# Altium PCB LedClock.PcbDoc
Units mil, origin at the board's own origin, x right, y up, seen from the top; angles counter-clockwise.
Board outline 2110 x 1975 mil, 2 copper layers (Top Layer, Bottom Layer); 29 components, 43 nets, 157 pads, 18 vias.
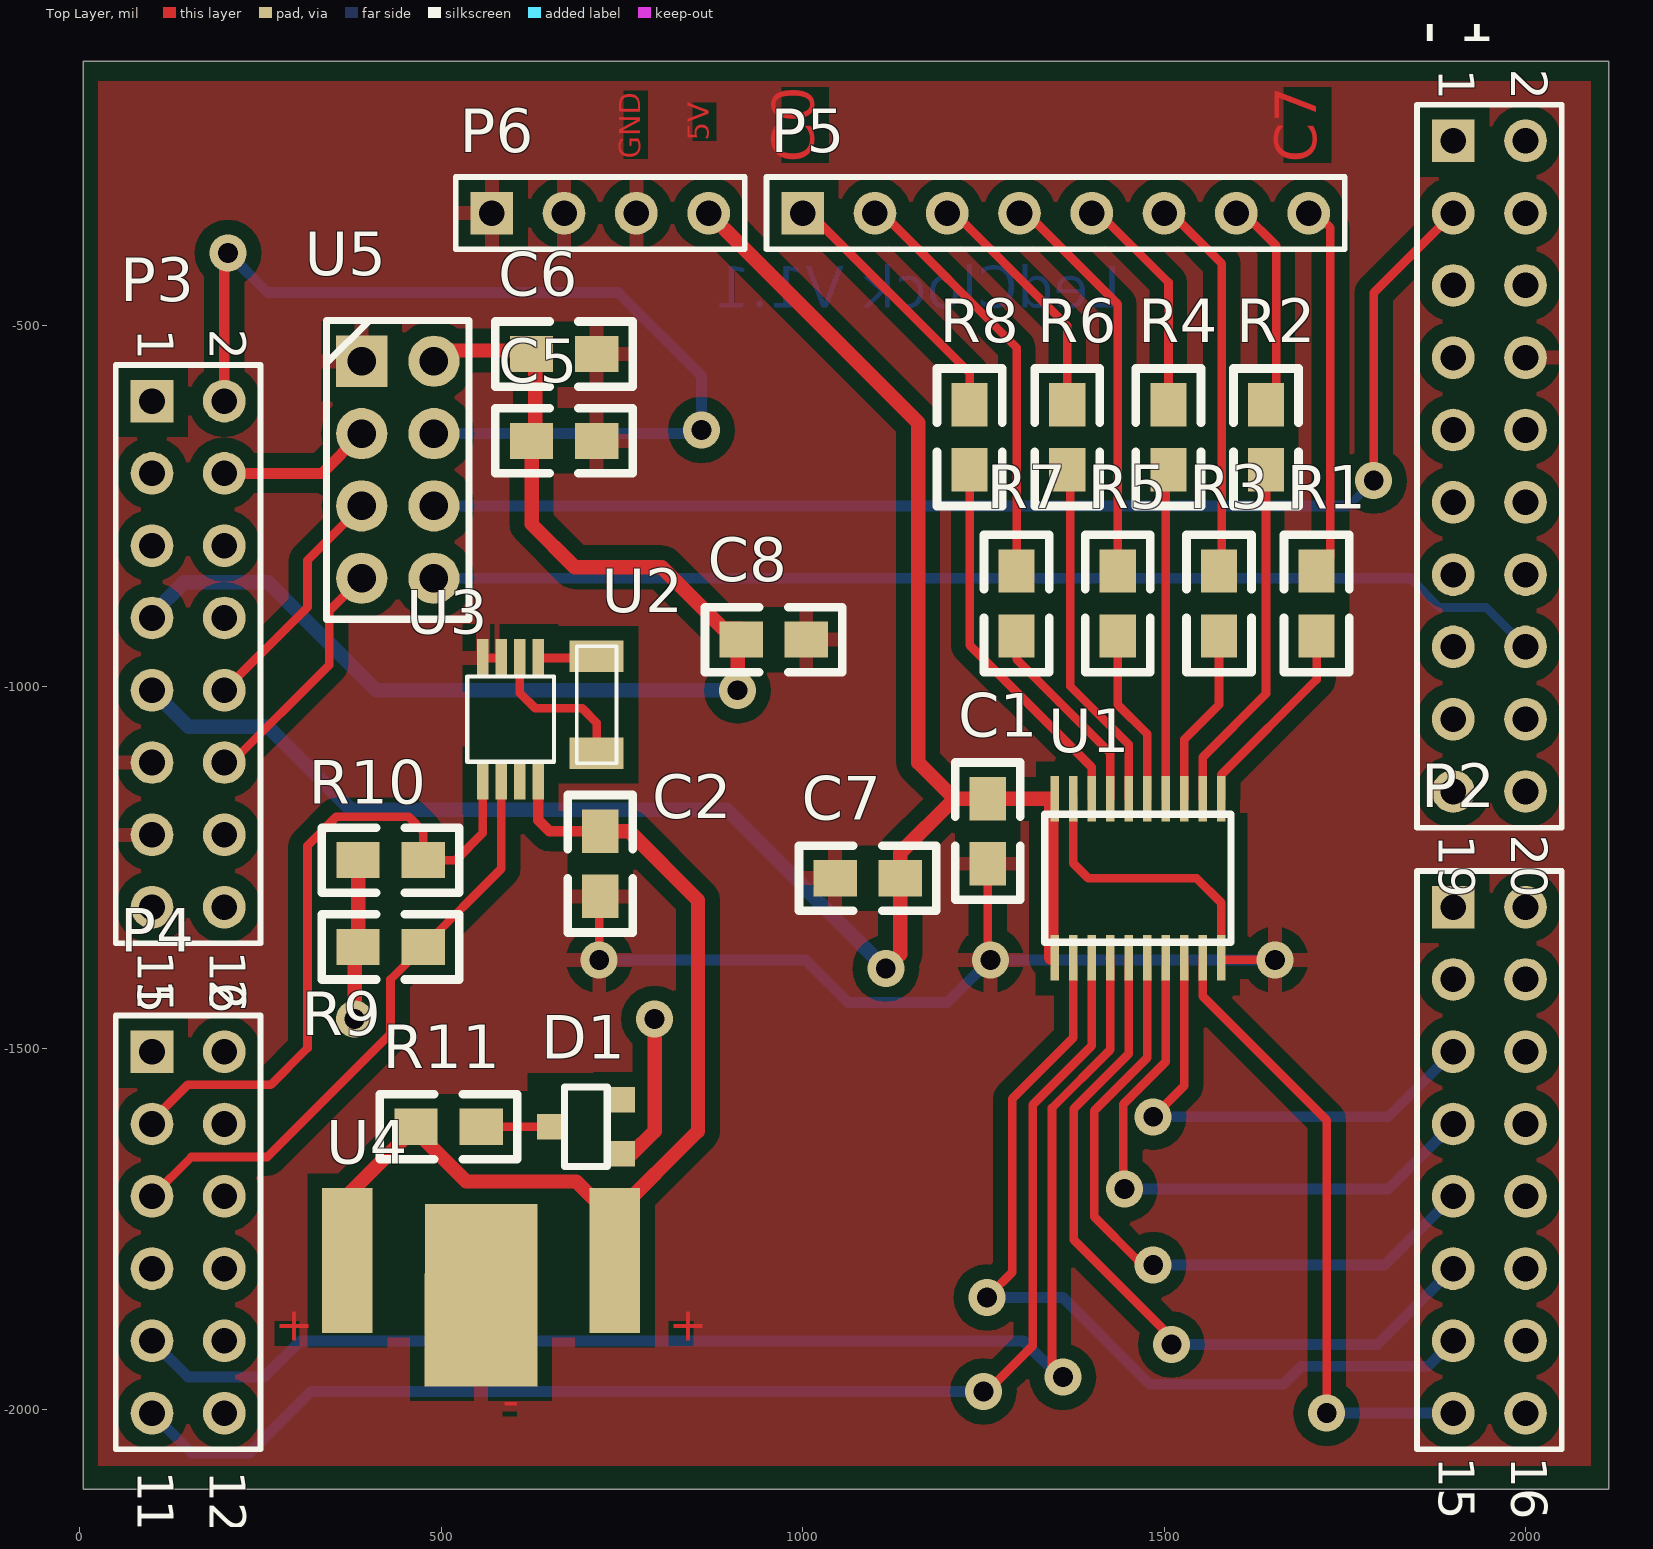
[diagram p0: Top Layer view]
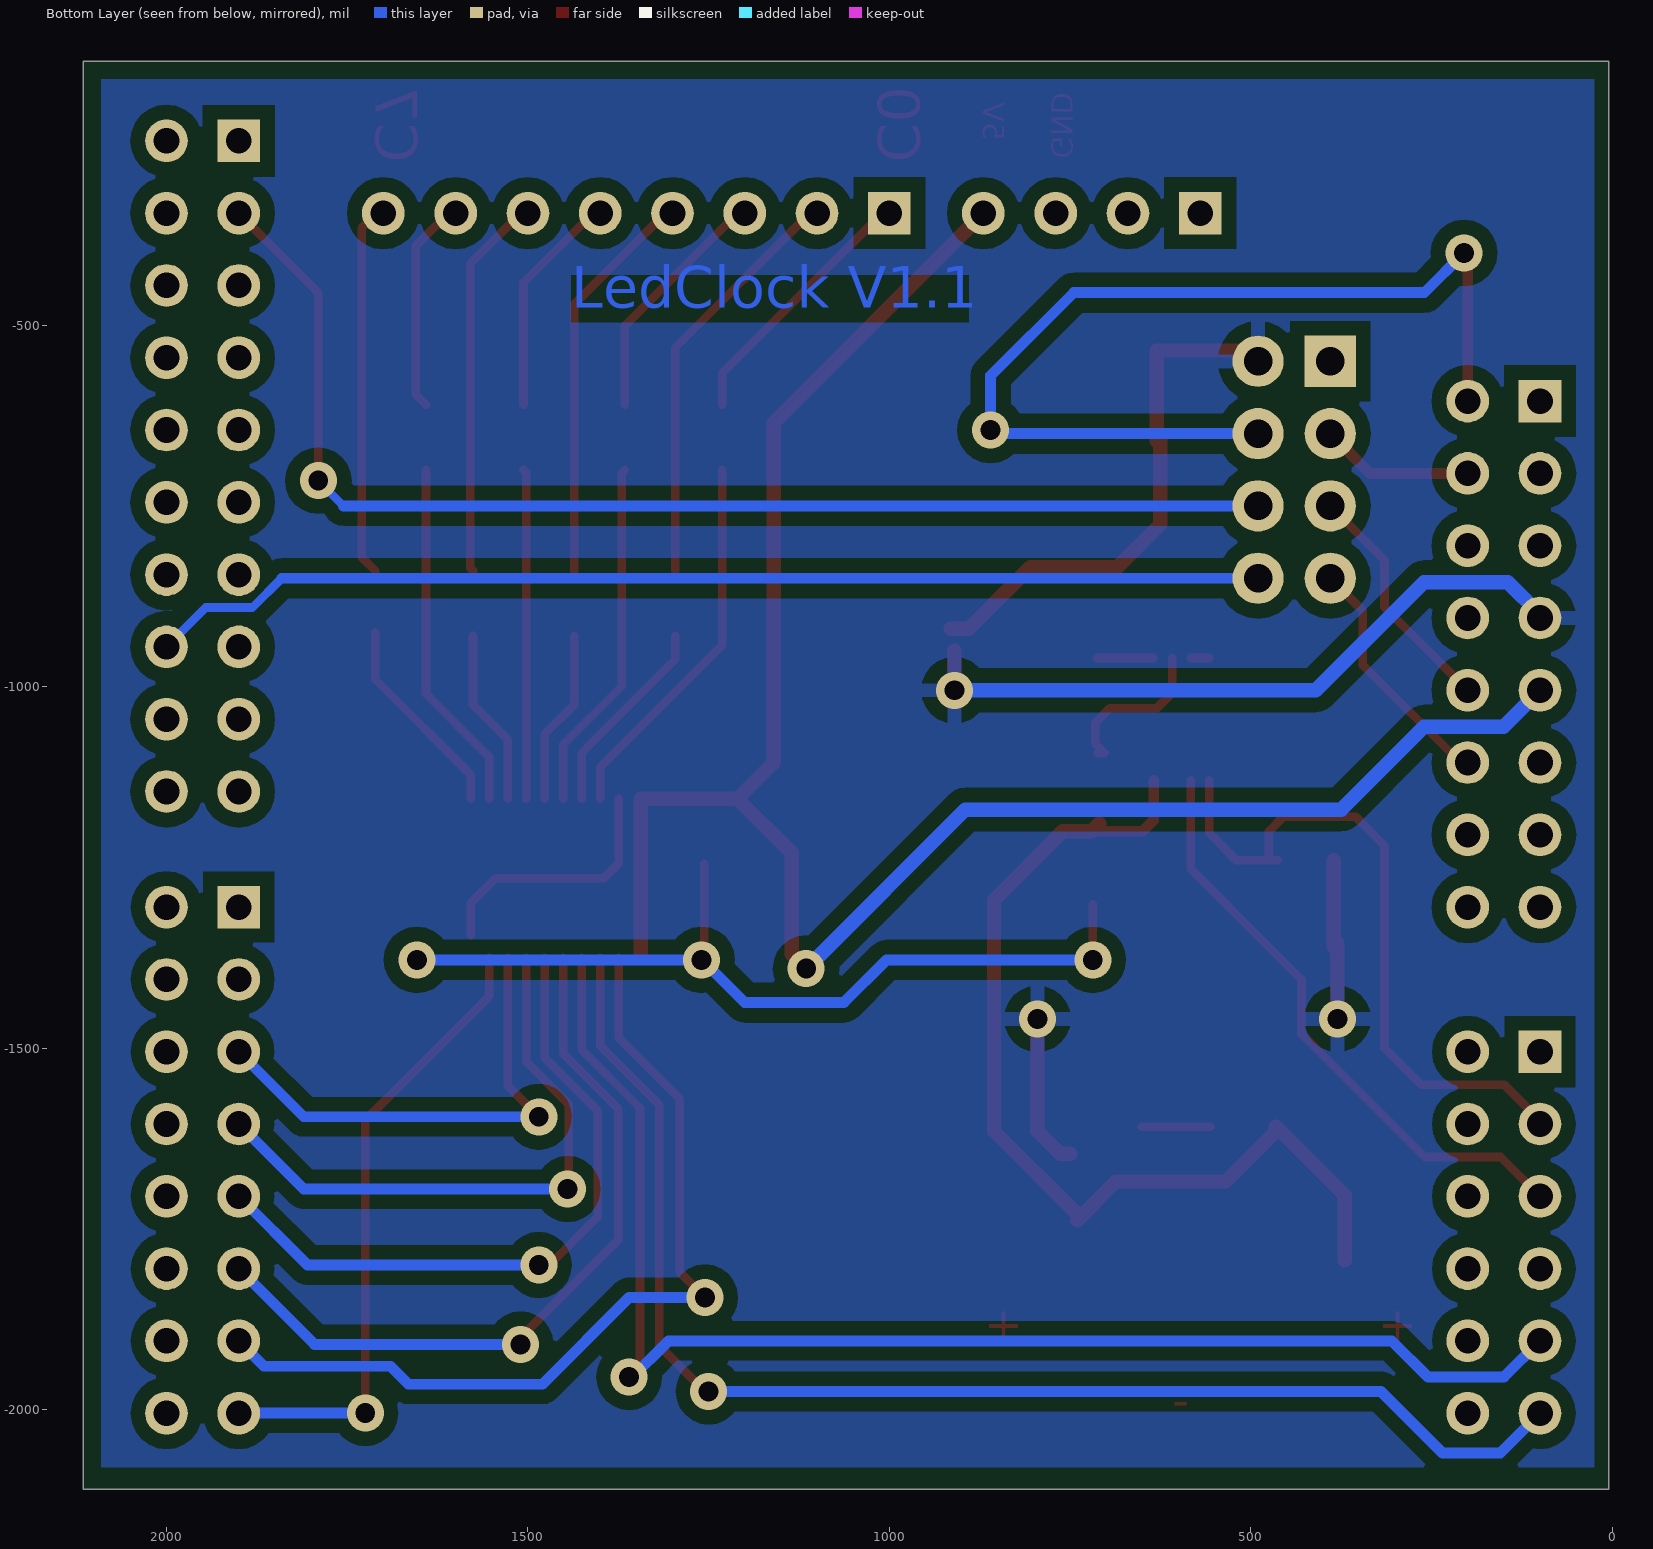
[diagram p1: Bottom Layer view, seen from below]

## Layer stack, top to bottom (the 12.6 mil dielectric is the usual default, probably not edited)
Top Layer: signal copper 1.4
Dielectric: dielectric 12.6, FR-4, Dk 4.8
Bottom Layer: signal copper 1.4

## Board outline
5,-135 2115,-135 2115,-2110 5,-2110

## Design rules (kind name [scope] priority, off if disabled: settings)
Clearance Clearance_Text [IsText] p1: gap=0
Clearance Clearance_Poly [InPolygon] p2: gap=20
Clearance Clearance_U1 [InComponent('U1')] p3: gap=7.83
Clearance Clearance_U3 [InComponent('U3')] p4: gap=7.83
Clearance [All] p5: gap=10
PlaneConnect [All] p1: planeconnectstyle=Relief reliefexpansion=20 reliefentries=4 reliefconductorwidth=20 reliefairgap=10
PolygonConnect [All] p1: connectstyle=Relief reliefconductorwidth=20 reliefentries=4 polygonreliefangle="90 Angle"
RoutingVias [All] p1: holewidth=28 width=50 viastyle="Through Hole" minholewidth=28 minwidth=50 maxholewidth=28 maxwidth=50
SilkscreenOverComponentPads [All] p1: minsilkscreentomaskgap=10
SolderMaskExpansion [All] p1: expansion=4
Width [All] p1: maxlimit=20 minlimit=12 preferedwidth=15
26 further rules are at their usual default settings.

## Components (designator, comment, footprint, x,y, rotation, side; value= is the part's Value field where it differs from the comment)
C1 "100nF" 0805 1256,-1155 r270 top
C2 "100nF" 0805 720,-1200 r270 top
C5 "1uF" 0805 715,-660 r180 top
C6 "100nF" 0805 715,-540 r180 top
C7 "100nF" 0805 1045,-1265 r0 top
C8 "100nF" 0805 1005,-935 r180 top
D1 "BAS40-04" SOT23 700.25,-1608.78 r90 top
P1 "Header 10X2" HDR2X10 1900,-245 r270 top
P2 "Header 8X2" HDR2X8 1900,-1305 r270 top
P3 "Header 8X2" HDR2X8 100,-605 r270 top
P4 "Header 6X2" HDR2X6 100,-1505 r270 top
P5 "Header 8" HDR1X8 1000,-345 r0 top
P6 "Header 4" HDR1X4 570,-345 r0 top
R1 "100" 0805 1711,-930 r90 top
R2 "100" 0805 1641,-700 r90 top
R3 "100" 0805 1576,-930 r90 top
R4 "100" 0805 1506,-700 r90 top
R5 "100" 0805 1436,-930 r90 top
R6 "100" 0805 1366,-700 r90 top
R7 "100" 0805 1296,-930 r90 top
R8 "100" 0805 1231,-700 r90 top
R9 "" 0805 475,-1360 r180 top
R10 "" 0805 475,-1240 r180 top
R11 "1k" 0805 555.25,-1608.78 r180 top
U1 "SN74HCT245PWR*" SN74HCT245PWR_20P 1451,-1265 r90 top
U2 "815-ABS09-32.7K-1-T" 815-ABS09-32.7K-1-T 715,-1025 r270 top
U3 "DS1342U+T&R" uSOP-8 595,-1045 r270 top
U4 "6.8mm SM Button Cell Retainer*" "6.8mm SM Button Cell Retainer" 555.25,-1793.78 r0 top
U5 "NRF24" HEADER2X4 440,-700 r270 top

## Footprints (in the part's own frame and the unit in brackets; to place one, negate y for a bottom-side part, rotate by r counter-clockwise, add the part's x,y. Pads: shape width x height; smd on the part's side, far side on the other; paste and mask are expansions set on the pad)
"6.8mm SM Button Cell Retainer" [mm]
  rect 1.78x5.08 smd: 1(-4.7,0) 1(4.7,0)
  rect 3.96x3.96 smd: 2(0,0)
  Top Layer pour cut-out: -3.75,2.65 3.75,2.65 3.75,-2.7 -3.75,-2.7
0805 [mil]
  rect 60x50 smd: 1(0,0) 2(90,0)
  silkscreen extent -50,-45 140,45
815-ABS09-32.7K-1-T [mm] "Quarze 32.768KHz 12.5pF -40C +85C 10ppm"
  rect 1.1x1.9 smd: 1(1.7,0) 2(-1.7,0)
  silkscreen extent -2.05,-0.7 2.05,0.7
HDR1X4 [mm] "Connector; Header; 4 Position"
  rect 1.5x1.5 hole 0.9: 1(0,0)
  round 1.5 hole 0.9: 2(2.54,0) 3(5.08,0) 4(7.62,0)
  silkscreen extent -1.27,-1.27 8.89,1.27
HDR1X8 [mm] "Connector; Header; 8 Position"
  rect 1.5x1.5 hole 0.9: 1(0,0)
  round 1.5 hole 0.9: 2(2.54,0) 3(5.08,0) 4(7.62,0) 5(10.16,0) 6(12.7,0) 7(15.24,0) 8(17.78,0)
  silkscreen extent -1.27,-1.27 19.05,1.27
HDR2X6 [mm] "Connector; Header; 6x2 Position"
  rect 1.5x1.5 hole 0.9: 1(0,0)
  round 1.5 hole 0.9: 2(0,2.54) 3(2.54,0) 4(2.54,2.54) 5(5.08,0) 6(5.08,2.54) 7(7.62,0) 8(7.62,2.54) 9(10.16,0) 10(10.16,2.54) 11(12.7,0) 12(12.7,2.54)
  silkscreen extent -1.27,-1.27 13.97,3.81
HDR2X8 [mm] "Connector; Header; 8x2 Position"
  rect 1.5x1.5 hole 0.9: 1(0,0)
  round 1.5 hole 0.9: 2(0,2.54) 3(2.54,0) 4(2.54,2.54) 5(5.08,0) 6(5.08,2.54) 7(7.62,0) 8(7.62,2.54) 9(10.16,0) 10(10.16,2.54) 11(12.7,0) 12(12.7,2.54) 13(15.24,0) 14(15.24,2.54) 15(17.78,0) 16(17.78,2.54)
  silkscreen extent -1.27,-1.27 19.05,3.81
HDR2X10 [mm] "Connector; Header; 10x2 Position"
  rect 1.5x1.5 hole 0.9: 1(0,0)
  round 1.5 hole 0.9: 2(0,2.54) 3(2.54,0) 4(2.54,2.54) 5(5.08,0) 6(5.08,2.54) 7(7.62,0) 8(7.62,2.54) 9(10.16,0) 10(10.16,2.54) 11(12.7,0) 12(12.7,2.54) 13(15.24,0) 14(15.24,2.54) 15(17.78,0) 16(17.78,2.54) 17(20.32,0) 18(20.32,2.54) 19(22.86,0) 20(22.86,2.54)
  silkscreen extent -1.27,-1.27 24.13,3.81
HEADER2X4 [mm] "Header 8Pin, 2x4, RM 2.54mm"
  rect 1.8x1.8 hole 1: 1(-3.81,-1.27)
  round 1.8 hole 1: 2(-1.27,-1.27) 3(1.27,-1.27) 4(3.81,-1.27) 5(3.81,1.27) 6(1.27,1.27) 7(-1.27,1.27) 8(-3.81,1.27)
  silkscreen extent -5.25,-2.5 5.25,2.5
SN74HCT245PWR_20P [mm]
  rect 1.6x0.3 smd mask+0.07: 1(-2.8,2.6) 2(-2.8,1.95) 3(-2.8,1.3) 4(-2.8,0.65) 5(-2.8,0) 6(-2.8,-0.65) 7(-2.8,-1.3) 8(-2.8,-1.95) 9(-2.8,-2.6) 10(-2.8,-3.25) 11(2.8,-3.25) 12(2.8,-2.6) 13(2.8,-1.95) 14(2.8,-1.3) 15(2.8,-0.65) 16(2.8,0) 17(2.8,0.65) 18(2.8,1.3) 19(2.8,1.95) 20(2.8,2.6)
  round 0.4 on Top Overlay: 1(-1.524,2.54)
  Top Layer pour cut-out: -2.15,2.85 2.15,2.85 2.15,-3.5 -2.15,-3.5
  silkscreen extent -2.25,-3.6 2.25,2.95
SOT23 [mm] "SOT-23"
  rect 0.9x0.95 smd: 1(-0.95,-1.25) 2(0.95,-1.25) 3(0,1.25)
  silkscreen extent -1.4,-0.75 1.4,0.75
uSOP-8 [mm] "3x3mm, 0.65mm"
  rect 1.35x0.4 smd: 1(-2.15,1) 2(-2.15,0.35) 3(-2.15,-0.3) 4(-2.15,-0.95) 5(2.15,-0.95) 6(2.15,-0.3) 7(2.15,0.35) 8(2.15,1)
  round 0.4 on Top Overlay: 3(-1.1,1.15)
  Top Layer pour cut-out: -1.45,1.5 1.45,1.5 1.45,-1.45 -1.45,-1.45
  silkscreen extent -1.5,-1.5 1.5,1.55

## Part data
C1 C2: library part CapNP, "Chip Capacitor SMD 0805"
C5 C6 C7 C8: library part C?, "Normaler Kondensator"
P1: "Header, 10-Pin, Dual row"
P2 P3: "Header, 8-Pin, Dual row"
P4: "Header, 6-Pin, Dual row"
P5: "Header, 8-Pin"
P6: "Header, 4-Pin"
R1 R2 R3 R4 R5 R6 R7 R8 R9 R10 R11: library part Res, "Chip Resistor SMD 0805"
U1: library part SN74HCT245PWR_20P
U4: library part "6.8mm SM Button Cell Retainer"

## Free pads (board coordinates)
  rect 155.91x155.91 smd: 0(555,-1890)

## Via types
v1: diameter 51.18, hole 27.56, Top Layer to Bottom Layer, 18 vias

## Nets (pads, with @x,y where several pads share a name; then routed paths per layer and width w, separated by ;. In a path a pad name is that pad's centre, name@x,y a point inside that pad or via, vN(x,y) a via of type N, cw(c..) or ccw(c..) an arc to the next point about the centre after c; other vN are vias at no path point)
GND: C1.2 C2.2 C5.1 C6.1 C7.1 C8.1 P1.8 P3.11 P3.13 P6.1 P6.2 P6.3 pad.0 U1.10 U1.19 U3.3@583.19,-960.35 U3.4 U4.2 U5.1 | length 1650.1
  Top Layer w12: U3.4 U3.3@583.19,-960.35 ; v1(718.66,-1377.95) C2.2@718.66,-1301.34 ; v1@1256,-1381 C1.2 ; U1.19 1374.23,-1244.23 1395,-1265 1545,-1265 1578.95,-1298.95 U1.10@1578.95,-1343.86 ; U1.10@1581.67,-1377.95 v1(1653.54,-1377.95)
  Bottom Layer w15: v1@720,-1380 722.05,-1377.95 1003.94,-1377.95 1062.99,-1437.01 1199.99,-1437.01 v1@1256,-1381 ; v1(1259.84,-1377.95) v1(1653.54,-1377.95)
NetC7_2: 
NetC8_2: 
NetD1_3: D1.3 R11.1 | length 95.8
  Top Layer w12: R11.1 D1.3
NetP1_3: P1.3 U5.6 | length 1749.2
  Top Layer w12: v1(1790,-715) 1790,-455 P1.3
  Bottom Layer w12: 1755,-750 v1(1790,-715) 1795,-715 v1@1805,-705
  Bottom Layer w15: U5.6 1755,-750
NetP1_8: 
NetP1_16: P1.16 U5.5 | length 1549.4
  Bottom Layer w12: 1840.61,-850 1881.14,-890.53 1945.53,-890.53 P1.16
  Bottom Layer w15: U5.5 1840.61,-850
NetP2_5: P2.5 U1.8 | length 694.5
  Top Layer w12: v1(1485,-1595) 1527.77,-1552.23 U1.8
  Bottom Layer w15: v1(1485,-1595) 1740,-1595 ; 1735.24,-1595 1810,-1595 P2.5
NetP2_7: P2.7 U1.7 | length 830.6
  Top Layer w12: v1@1443.41,-1693.41 1443.41,-1577.77 1502.18,-1519 U1.7
  Bottom Layer w15: v1(1445,-1695) 1740,-1695 ; 1744.24,-1695 1810,-1695 P2.7
NetP2_9: P2.9 U1.6 | length 945.2
  Top Layer w12: U1.6 1476.59,-1513.48 1403.41,-1586.66 1403.41,-1733.41 1463.82,-1793.82 v1@1485,-1793.82
  Bottom Layer w15: v1(1485,-1800) 1735,-1800 ; 1739.24,-1800 1805,-1800 P2.9
NetP2_11: P2.11 U1.5 | length 1060.4
  Top Layer w12: U1.5 1451,-1507.96 1375,-1583.96 1375,-1765 1510,-1900 v1(1510,-1910)
  Bottom Layer w15: v1(1510,-1910) 1725,-1910 ; 1720.24,-1910 1795,-1910 P2.11
NetP2_13: P2.13 U1.2 | length 1231.6
  Top Layer w12: v1@1260,-1840 1290,-1810 1290,-1570 1374.23,-1485.77 U1.2
  Bottom Layer w15: v1(1255,-1845) 1360,-1845 1480,-1965 1665,-1965 1690,-1940 1865,-1940 P2.13
NetP2_15: P2.15 U1.9 | length 875.9
  Top Layer w12: U1.9 1553.36,-1428.36 1725,-1600 v1(1725,-2005)
  Bottom Layer w15: v1(1725,-2005) P2.15
NetP3_2: P3.2 U5.7 | length 1370.4
  Top Layer w15: P3.2 v1@200,-400
  Bottom Layer w15: v1(205,-400) 260,-455 745,-455 860,-570 v1(860,-645) ; U5.7 v1@855,-650
NetP3_4: P3.4 U5.2 | length 212.8
  Top Layer w15: P3.4 335,-705 U5.2
NetP3_10: P3.10 U5.3 | length 367.6
  Top Layer w12: P3.10 315,-890 315,-825 U5.3
  Top Layer w15: U5.3@390,-775 U5.3
  Bottom Layer w12: P3.10 P3.10@200,-996.06
NetP3_12: P3.12 U5.4 | length 368.5
  Top Layer w12: P3.12@200,-1096.06 P3.12 210,-1105 345,-970 345,-895 U5.4
  Top Layer w15: U5.4@370,-850 U5.4
NetP4_3: P4.3 R10.1 U3.5 | length 945.4
  Top Layer w12: P4.3@110,-1605 110,-1590 149.47,-1550.53 264.47,-1550.53 315,-1500 315,-1220 355,-1180 455,-1180 475,-1200 R10.1 ; R10.1@462.63,-1240 R10.1 ; U3.5 557.6,-1202.4 520,-1240 R10.1
NetP4_5: P4.5 R9.1 U3.6 | length 837
  Top Layer w12: P4.5 154.47,-1650.53 259.47,-1650.53 430,-1480 430,-1405 R9.1 583.19,-1251.81 U3.6
NetP4_9: P4.9 U1.4 | length 1933.9
  Top Layer w12: v1@1353,-1948 1345,-1940 1345,-1582.84 1425.41,-1502.43 U1.4 U1.4@1425,-1375.65
  Bottom Layer w15: P4.9 150,-1955 255,-1955 305,-1905 1305.53,-1905 v1@1360,-1959.47
  other v1: 1360,-1955
NetP4_11: P4.11 U1.3 | length 1869.5
  Top Layer w12: v1@1257.5,-1972.5 1318.41,-1911.59 1318.41,-1578.32 1399.82,-1496.91 U1.3 U1.3@1400,-1375.42
  Bottom Layer w15: P4.11 155,-2060 235,-2060 320,-1975 v1@1255,-1975
  other v1: 1250,-1975
NetP5_1: P5.1 R8.2 | length 356.5
  Top Layer w12: P5.1@1010,-345 1231,-566 R8.2
NetP5_2: P5.2 R7.2 | length 572
  Top Layer w12: P5.2@1110,-345 1296,-531 R7.2
NetP5_3: P5.3 R6.2 | length 329.6
  Top Layer w12: P5.3@1210,-345 1366,-501 R6.2
NetP5_4: P5.4 R5.2 | length 547.2
  Top Layer w12: P5.4@1310,-345 1436,-471 R5.2
NetP5_5: P5.5 R4.2 | length 304.8
  Top Layer w12: P5.5@1410,-345 1506,-441 R4.2
NetP5_6: P5.6 R3.2 | length 525.7
  Top Layer w12: P5.6@1510,-345 1580,-415 1580,-836 R3.2
NetP5_7: P5.7 R2.2 | length 289.4
  Top Layer w12: P5.7@1610,-345 1655,-390 1655,-596 R2.2
NetP5_8: P5.8 R1.2 | length 511.2
  Top Layer w12: P5.8@1710,-345 1730,-365 1730,-821 R1.2
NetR1_1: R1.1 U1.11 | length 284.5
  Top Layer w12: U1.11 1578.95,-1122.05 1711,-990 R1.1 R1.1@1711,-925
NetR2_1: R2.1 U1.12 | length 491.1
  Top Layer w12: U1.12 1553.36,-1097.64 1641,-1010 R2.1
NetR3_1: R3.1 U1.13 | length 244.7
  Top Layer w12: U1.13 1527.77,-1073.23 1576,-1025 R3.1
NetR4_1: R4.1 U1.14 | length 456.3
  Top Layer w12: U1.14 1502.18,-703.82 R4.1
NetR5_1: R5.1 U1.15 | length 241.6
  Top Layer w12: R5.1 1436,-1025 1476.59,-1065.59 U1.15
NetR6_1: R6.1 U1.16 | length 490
  Top Layer w12: R6.1 1370,-704 1370,-999 1451,-1080 U1.16
NetR7_1: R7.1 U1.17 | length 278.4
  Top Layer w12: R7.1 1296,-962.23 1425.41,-1091.63 U1.17
NetR8_1: R8.1 U1.18 | length 524.7
  Top Layer w12: R8.1 1231,-942.63 1399.82,-1111.45 U1.18
NetR11_2: 
NetU2_1: U2.1 U3.2 | length 229.1
  Top Layer w12: U3.2 608.78,-1008.78 630,-1030 695,-1030 715,-1050 715,-1078.86 701.93,-1091.93 U2.1@711.93,-1091.93
NetU2_2: U2.2 U3.1 | length 78.3
  Top Layer w12: U3.1 U2.2@712.72,-960.35
VCC_3.3V: C5.2 C6.2 C8.2 D1.1 P3.7 R9.2 R10.2 U5.8 | length 2131.7
  Top Layer w20: v1(380.25,-1459.53) 380.25,-1355.25 R9.2 R10.2 ; U5.8 505,-535 630,-535 C5.2@630,-660 ; C5.2 625,-775 685,-835 805,-835 890,-920 C8.2@915,-920 ; D1.1 763.82,-1646.18 795.25,-1614.75 v1(795.25,-1459.53) ; v1(910,-1005) C8.2@910,-950
  Bottom Layer w20: P3.7 100,-900 144.53,-855.47 260.47,-855.47 410,-1005 v1(910,-1005)
VCC_5V: C1.1 C7.2 P3.9 P6.4 U1.1@1348.64,-1375.24 U1.20 | length 2722.2
  Top Layer w20: 892.12,-367.12 1160,-635 1160,-1105 1210,-1155 ; v1(1115,-1390) 1135,-1370 C7.2 1135,-1230 1210,-1155 ; U1.1@1343.64,-1375.24 1343.64,-1155 C1.1 1210,-1155
  Bottom Layer w20: P3.9 150.47,-1055.47 260.47,-1055.47 375,-1170 895,-1170 v1(1115,-1390)
VCC_BAT: C2.1 R11.2 U3.8 U4.1 | length 1374.2
  Top Layer w15: U3.8 634.37,-1184.37 650,-1200 C2.1
  Top Layer w20: U4.1@370.21,-1793.78 370.21,-1703.82 R11.2@464.51,-1609.51 ; R11.2 465.25,-1615.25 534.53,-1684.53 686.66,-1684.53 U4.1@740.29,-1738.16 ; C2.1@709.53,-1189.53 C2.1 760,-1200 855.25,-1295.24 855.25,-1614.75 U4.1@740.29,-1729.71
pads on no net: D1.2 P1.1 P1.2 P1.4 P1.5 P1.6 P1.7 P1.9 P1.10 P1.11 P1.12 P1.13 P1.14 P1.15 P1.17 P1.18 P1.19 P1.20 P2.1 P2.2 P2.3 P2.4 P2.6 P2.8 P2.10 P2.12 P2.14 P2.16 P3.1 P3.3 P3.5 P3.6 P3.8 P3.14 P3.15 P3.16 P4.1 P4.2 P4.4 P4.6 P4.7 P4.8 P4.10 P4.12 U1.1@1351,-1325 U3.3@640.28,-1001.69 U3.7

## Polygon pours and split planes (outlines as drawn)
VCC_3.3V on Bottom Layer "Mechanical 1-No Net" (solid, pour order 4): 25,-160 2090,-160 2090,-2080 25,-2080 25,-160
GND on Top Layer "Mechanical 1-No Net" (solid, pour order 3): 25.48,-162.8 2090.48,-162.8 2090.48,-2077.8 25.48,-2077.8 25.48,-162.8

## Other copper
Top Layer:
  pour cut-out: 585,-1560 645,-1560 645,-1600 585,-1600
  pour cut-out: 735,-990 740.84,-984.16 772.4,-984.16 772.4,-1077.6 770,-1080 765,-1075 735,-1075
  pour cut-out: 1615,-1365 1615,-1175 1560,-1175 1560,-1365
  pour cut-out: 620,-1535 785,-1535 785,-1675 625,-1675 620,-1670
  pour cut-out: 670,-945 760,-945 760,-1095 755,-1100 670,-1100
  text "5V" at 880,-245 h50 r90
  text "GND" at 785,-270 h50 r90
  text "C0" at 1035,-275 h98.43 r90
  text "C7" at 1730,-275 h98.43 r90
  text "+" at 270,-1920 h80
  text "+" at 815,-1920 h80
  text "-" at 585,-2024.46 h80
Bottom Layer:
  text "LedClock V1.1" at 1440,-495 h98.43

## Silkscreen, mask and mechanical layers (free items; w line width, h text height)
Mechanical 1:
  lines w20: -5,-2110 -5,-130 2125,-130 2125,-2110 -5,-2110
